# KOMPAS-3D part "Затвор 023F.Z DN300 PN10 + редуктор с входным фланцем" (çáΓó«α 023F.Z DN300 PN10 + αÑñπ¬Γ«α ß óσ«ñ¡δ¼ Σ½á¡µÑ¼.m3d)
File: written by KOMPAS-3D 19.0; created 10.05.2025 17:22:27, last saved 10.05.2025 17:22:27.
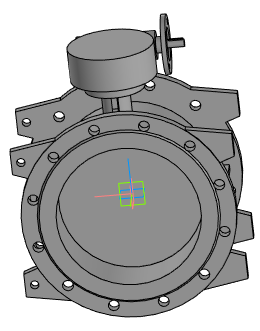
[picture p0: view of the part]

Document properties: Полное имя файла: Затвор 023F.Z DN300 PN10 + редуктор с входным фланцем.a3d

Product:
- Part/product: Затвор 023F.Z DN300 PN10 + редуктор с входным фланцем
    Масса: 98.7634

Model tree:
1. Операция без истории:1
